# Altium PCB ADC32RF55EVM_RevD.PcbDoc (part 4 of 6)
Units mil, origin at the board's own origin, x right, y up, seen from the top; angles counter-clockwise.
Board outline 4190 x 2750 mil, 14 copper layers (Top Copper, Layer 2 (GND1), Layer 3 (PWR1), Layer 4 (GND2, Layer 5 (PWR2), Layer 6 (GND3), Layer 7 (SIG1), Layer 8 (GND4), Layer 9 (GND5), Layer 10 (SIG2), Layer 11 (GND6), Layer 12 (PWR3), Layer 13 (GND7), Bottom Copper), stack 58.6 mil thick; 427 components, 558 nets, 1902 pads, 1008 vias.
Unrouted connection lines stored in the file: 51.
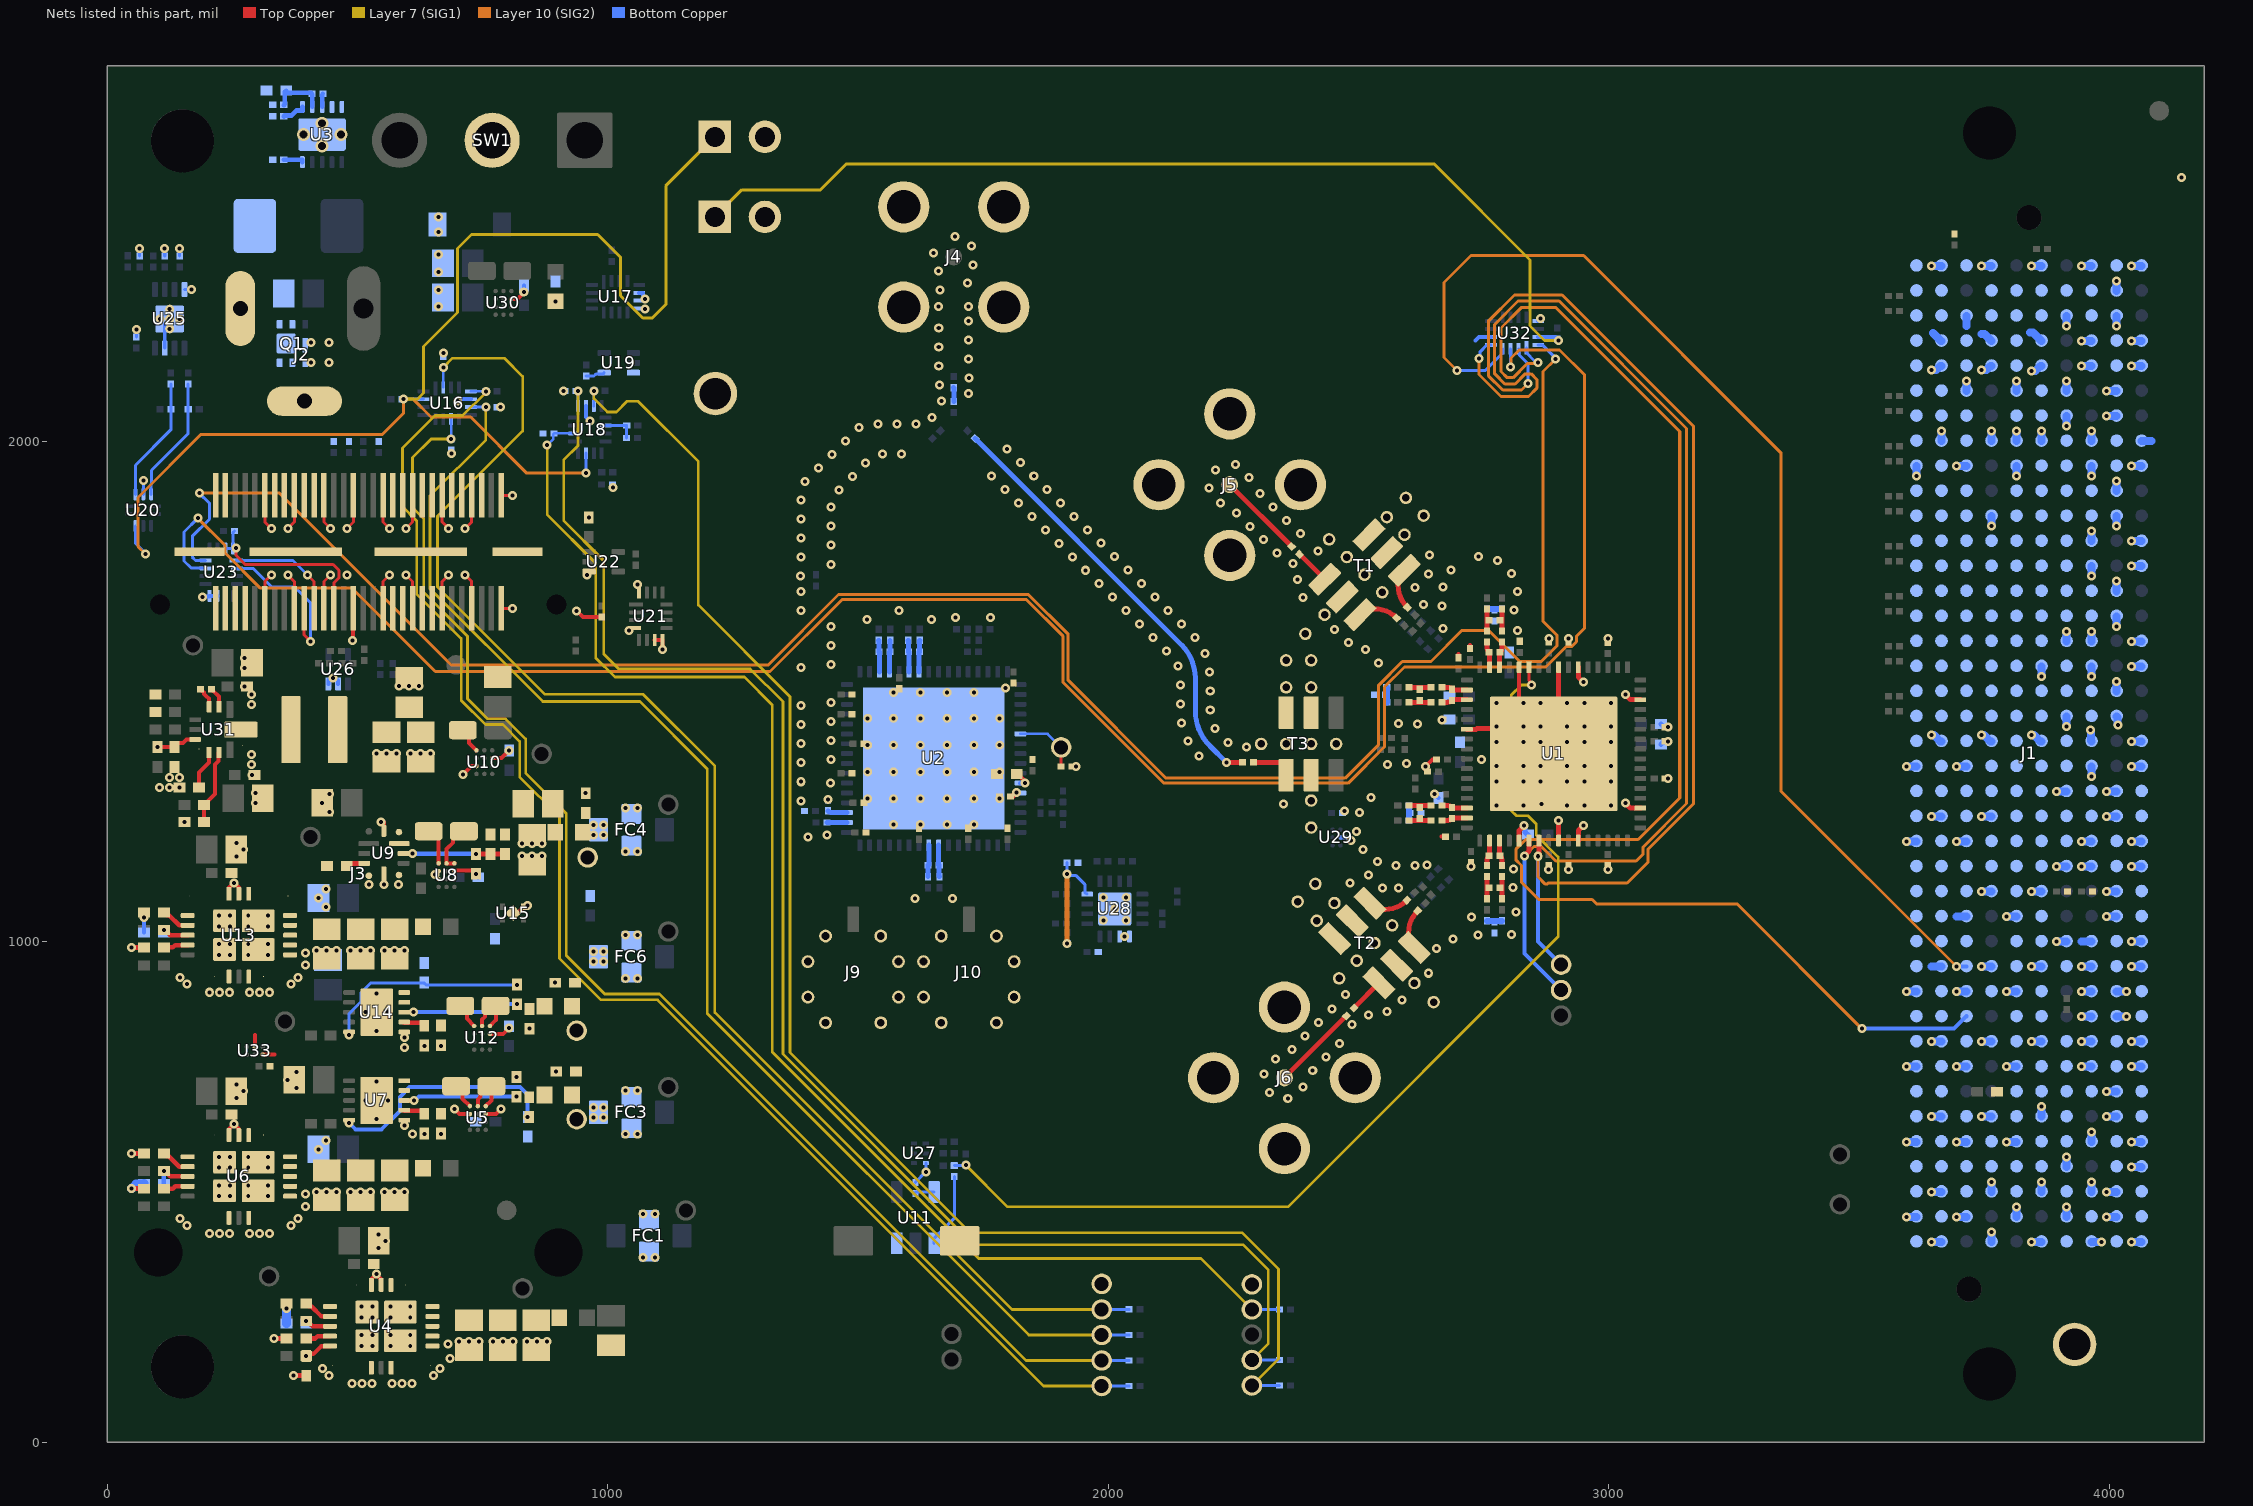
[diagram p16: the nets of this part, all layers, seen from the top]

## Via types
v1: diameter 18, hole 8, Top Copper to Bottom Copper, tented both sides, 1004 vias
v2: diameter 25.75, hole 15.75, Top Copper to Bottom Copper, tented both sides, 4 vias

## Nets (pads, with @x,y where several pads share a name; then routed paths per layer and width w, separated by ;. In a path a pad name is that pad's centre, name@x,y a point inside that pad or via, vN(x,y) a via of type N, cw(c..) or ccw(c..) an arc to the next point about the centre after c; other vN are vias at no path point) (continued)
GND: C1.1 C3.2 C4.2 C5.1 C6.1 C7.1 C8.1 C9.1 C10.1 C11.1 C12.1 C13.1 C14.1 C15.1 C16.1 C17.1 C18.1 C19.1 C20.1 C21.1 C22.1 C23.1 C24.1 C25.1 C26.1 C27.1 C28.1 C29.1 C30.1 C31.1 C32.1 C33.1 C35.1 C39.1 C40.1 C41.1 C42.1 C43.1 C44.1 C45.1 C46.1 C50.1 C51.1 C52.1 C53.1 C54.1 C55.1 C56.1 C57.1 C59.1 C60.1 C64.1 C65.1 C67.1 C71.1 C76.1 C82.1 C91.1 C92.1 C108.1 C109.1 C110.1 C111.1 C112.1 C113.1 C114.1 C115.1 C116.1 C117.1 C118.1 C119.1 C120.1 C121.1 C122.1 C123.1 C124.1 C125.1 C126.1 C127.1 C128.1 C129.1 C130.1 C131.1 C132.1 C139.2 C140.2 C141.2 C142.2 C143.2 C144.2 C145.2 C146.2 C147.2 C148.2 C149.1 C150.1 C151.2 C152.2 C156.1 C159.1 C160.1 C165.1 C166.1 C177.1 C178.1 D2.2 FC1.2 FC3.2 FC4.2 FC6.2 J1.A1 J1.A4 J1.A5 J1.A8 J1.A9 J1.A12 J1.A13 J1.A16 J1.A17 J1.A20 J1.A21 J1.A24 J1.A25 J1.A28 J1.A29 J1.A32 J1.A33 J1.A36 J1.A37 J1.A40 J1.B2 J1.B3 J1.B6 J1.B7 J1.B10 J1.B11 J1.B14 J1.B15 J1.B18 J1.B19 J1.B22 J1.B23 J1.B26 J1.B27 J1.B30 J1.B31 J1.B34 J1.B35 J1.B38 J1.B39 J1.C1 J1.C4 J1.C5 J1.C8 J1.C9 J1.C12 J1.C13 J1.C16 J1.C17 J1.C20 J1.C21 J1.C24 J1.C25 J1.C28 J1.C29 J1.C32 J1.C33 J1.C36 J1.C38 J1.C40 J1.D2 J1.D3 J1.D6 J1.D7 J1.D10 J1.D13 J1.D16 J1.D19 J1.D22 J1.D25 J1.D28 J1.D37 J1.D39 J1.E1 J1.E4 J1.E5 J1.E8 J1.E11 J1.E14 J1.E17 J1.E20 J1.E23 J1.E26 J1.E29 J1.E32 J1.E35 J1.E38 J1.E40 J1.F6 J1.F9 J1.F21 J1.F27 J1.F30 J1.F33 J1.F36 J1.F39 J1.G1 J1.G4 J1.G5 J1.G8 J1.G11 J1.G20 J1.G23 J1.G26 J1.G29 J1.G32 J1.G35 J1.G38 J1.G40 J1.H3 J1.H6 J1.H9 J1.H12 J1.H15 J1.H18 J1.H21 J1.H24 J1.H27 J1.H30 J1.H33 J1.H36 J1.H39 J1.J1 J1.J4 J1.J5 J1.J8 J1.J11 J1.J14 J1.J17 J1.J20 J1.J23 J1.J26 J1.J29 J1.J32 J1.J35 J1.J38 J1.J40 J1.K2 J1.K3 J1.K6 J1.K9 J1.K12 J1.K15 J1.K18 J1.K21 J1.K24 J1.K27 J1.K30 J1.K33 J1.K36 J1.K39 J3.1 J3.2 J3.7 J3.8 J3.13 J3.14 J3.19 J3.20 J3.25 J3.26 J3.31 J3.32 J3.37 J3.38 J3.43 J3.44 J3.49 J3.50 J3.MP1 J3.MP2 J3.MP3 J3.MP4 J4.2 J4.3 J4.4 J4.5 J5.2 J5.3 J5.4 J5.5 J6.2 J6.3 J6.4 J6.5 J7.2 J8.2 J9.2 J10.2 PP14.1 PP19.1 Q1.4 Q1.7 R3.1 R4.2 R7.2 R8.2 R9.1 R10.1 R15.1 R17.1 R18.1 R19.1 R22.1 R30.1 R35.1 R37.1 R38.1 R39.1 R42.2 R43.2 R44.2 R50.2 R51.2 R52.2 R53.2 R54.2 R63.2 R64.2 R75.2 R78.1 R79.2 R83.1 R85.1 R94.2 R95.2 R96.2 R140.1 R145.1 R154.2 R181.1 R182.1 SW3.1 T1.1 T1.2 T1.5 T2.1 T2.2 T2.5 T3.1 T3.2 T3.5 TP3.1 TP4.1 U1.6 U1.8 U1.12 U1.22 U1.37 U1.41 U1.43 U1.51 U1.62 U1.65 U2.65 U3.11 U4.1 U4.2 U4.3 U4.5 U4.6 U4.7 U4.8 U4.9 U4.16 U4.17 U4.20 U4.25 U4.26 U4.28 U5.C1 U5.C3 U6.1 U6.2 U6.3 U6.5 U6.6 U6.7 U6.8 U6.9 U6.16 U6.17 U6.20 U6.25 U6.26 U6.28 U7.6 U7.11 U8.B3 U8.C1 U8.C3 U9.5 U9.6 U9.7 U9.12 U10.B3 U10.C1 U11.3 U12.C1 U13.1 U13.2 U13.3 U13.5 U13.6 U13.7 U13.8 U13.9 U13.16 U13.17 U13.20 U13.25 U13.26 U13.28 U14.6 U14.11 U15.2 U15.5 U16.6 U17.6 U17.7 U17.8 U18.6 U19.3 U20.4 U21.4 U21.7 U21.8 U21.16 U22.3 U23.7 U23.8 U25.4 U25.7 U25.9 U26.2 U26.3 U27.3 U28.1 U28.2 U28.17 U29.B2 U30.C1 U31.5 U31.9 U31.11 U32.6 U32.13 U33.B2 U33.C1 | length 5811.2
  Top Copper w6: J3.50@314.74,1666 314.74,1719.39 v1(327.78,1732.43) ; J3.49@314.74,1891.59 314.74,1838.2 v1(327.78,1825.16) ; v1(360.76,1732.43) 373.8,1719.39 J3.44@373.8,1666 ; v1(360.76,1825.16) 373.8,1838.2 J3.43@373.8,1891.59 ; J3.38@432.85,1666 432.85,1719.39 v1(445.89,1732.43) ; J3.37@432.85,1891.59 432.85,1838.2 v1(445.89,1825.16) ; v1(478.87,1825.16) 491.91,1838.2 J3.31@491.91,1891.59 ; J3.26@550.96,1666 550.96,1719.39 v1(564,1732.43) ; J3.25@550.96,1891.59 550.96,1838.2 v1(564,1825.16) ; v1(596.98,1732.43) 610.02,1719.39 J3.20@610.02,1666 ; v1(596.98,1825.16) 610.02,1838.2 J3.19@610.02,1891.59 ; J3.14@669.07,1666 669.07,1719.39 v1(682.11,1732.43) ; J3.13@669.07,1891.59 669.07,1838.2 v1(682.11,1825.16) ; v1(715.09,1732.43) 728.13,1719.39 J3.8@728.13,1666 ; v1(715.09,1825.16) 728.13,1838.2 J3.7@728.13,1891.59 ; J3.2@787.18,1666 v1(810,1666) ; J3.1@787.18,1891.59 v1(810,1891.59)
  Top Copper w8: U6.17@243.24,613.31 243.24,625.46 v1(253.09,635.31) 262.93,625.46 U6.16@262.93,613.31 ; U13.17@243.24,1095.5 243.24,1107.66 v1(253.09,1117.5) 262.93,1107.66 U13.16@262.93,1095.5 ; U33.B2@294.75,789.75 294.75,813.75 ; U33.C1@310.5,774 334.5,774 ; v1(490,1602) 490.95,1602.95 490.95,1665.05 J3.32@491.91,1666 ; U4.17@527.67,313.95 527.67,326.11 v1(537.51,335.95) 547.36,326.11 U4.16@547.36,313.95 ; v1(547.02,1238.89) 552.73,1238.89 U9.12@552.73,1221.22 ; U8.B3@662.18,1124.89 662.18,1125.12 655.26,1132.04 v1(655.26,1133.63) U8.C3@662.18,1140.64 ; U8.C1@693.68,1140.64 693.91,1140.64 695.1,1141.83 731.09,1141.83 736.94,1135.99 v1(736.94,1135.44) ; v1(693.91,665.28) 703.82,655.37 U5.C3@724.7,655.37 ; v1(711,1333.5) 728.04,1350.54 737.52,1350.54 U10.B3@737.68,1350.71 ; U5.C1@756.19,655.37 777.07,655.37 v1(786.98,665.28) ; U12.C1@764.63,815.58 791.19,815.58 v1(802.7,827.09) v1@802.61,827.18 ; U10.C1@769.18,1366.46 787.92,1366.46 v1(803.14,1381.67) ; U30.C1@807.43,2284.09 819.94,2284.09 v1@832.17,2296.33 ; v1(938,1661) 950.57,1648.43 R85.1@988.21,1648.43 ; v1(1042.33,1621.68) 1042.33,1626.38 U21.4@1054.5,1626.38 ; v1(1059.18,1713.8) 1062.38,1713.8 U21.16@1062.38,1697.24 ; U21.7@1093.87,1602.76 U21.8@1109.62,1602.76 1109.62,1583.87 v1(1109.69,1583.8) ; R154.2@1930.5,1350 v1(1935.5,1350) ; C92.1@2637.95,1340 2633.94,1344.02 v1(2633.94,1350.32) 2647.62,1364 C121.1@2656.95,1364 ; 2666.44,1209.72 C160.1@2671.44,1209.72 ; C111.1@2700,1569.5 2700,1574.5 ; C117.1@2722.96,1588.03 2722.96,1593.03 ; v1(2725,1150.5) C118.1@2725,1155.5 ; U1.12@2821.1,1548.23 2821.1,1485.33 v1(2829.34,1477.17) v1(2829.34,1477.17) ; v1(2880.16,1144.49) C129.1@2880.16,1149.49 ; C130.1@2880.43,1600.74 v1(2880.43,1605.74) ; v1(2919.53,1144.49) C127.1@2919.53,1149.49 ; C126.1@2919.8,1600.74 v1(2919.8,1605.74) ; v1(2998.25,1144.47) C131.1@2998.25,1149.47 ; C128.1@2998.27,1600.51 v1(2998.27,1605.51) ; C125.1@3113.06,1325.79 v1(3118.06,1325.79)
  Top Copper w10: v1(48.7,506.26) R15.1@73.7,506.26 ; v1(48.7,576.26) C30.1@73.7,576.26 ; v1(48.7,988.45) R35.1@73.7,988.45 ; v1(73.7,1048.45) C33.1@73.7,1058.45 ; v1(333.12,206.91) R9.1@358.12,206.91 ; v1(358.12,266.91) C15.1@358.12,276.91 ; v1(372.49,132.54) R8.2@397.49,132.54 ; U15.5@810.94,1056.8 820.01,1056.8 833.51,1070.29 838.6,1070.29 v1(840.13,1071.82) ; C149.1@1777.99,1334.82 1782.23,1339.05 U2.65@1783.2,1339.05 ; U1.22@2716.77,1424.21 2735.26,1424.21 2736.54,1425.5 2771.91,1425.5 v1(2776.27,1429.86) ; U1.37@2821.1,1201.77 2821.1,1221.77 v1(2831.1,1231.77) ; U1.41@2899.84,1201.77 v1(2899.84,1241.77) ; U1.8@2899.84,1548.23 2899.84,1484.33 2907,1477.17 v1(2916.82,1477.17) ; U1.43@2939.21,1201.77 2939.21,1221.77 v1(2949.21,1231.77) ; U1.6@2939.21,1548.23 2939.21,1528.23 v1(2949.21,1518.23) ; v1(3033.23,1276.73) 3043.23,1266.73 U1.51@3063.23,1266.73 ; v1(3033.23,1493.27) 3043.23,1483.27 U1.62@3063.23,1483.27
  Bottom Copper w6: v1(58.12,2222.57) 58.2,2222.48 C67.1@58.2,2208.02 ; v1(64.76,2384.76) 64.84,2384.67 R94.2@64.84,2370.21 ; U20.4@72,1893.5 72.4,1893.89 v1(72.4,1921.7) ; v1(114.76,2384.65) v1(114.76,2384.65) R95.2@114.84,2370.1 ; U25.7@114.84,2185.8 114.84,2234.16 U25.9@124.68,2244 ; v1(144.44,2384.65) 144.53,2384.56 R96.2@144.53,2370.1 ; U25.4@154.21,2303.06 168.67,2303.06 v1(168.76,2303.14) ; C44.1@1614.89,518.55 1614.89,519.33 v1(1635.56,540.01) U27.3@1635.56,557.23
  Bottom Copper w7.87: R39.1@73.7,1018.45 v1(73.7,1048.45)
  Bottom Copper w8: v1(190,1689) 190.88,1689.88 204.31,1689.88 204.38,1689.94 U23.8@204.38,1690.76 ; U23.8@204.38,1690.76 U23.7@220.13,1690.76 ; U26.3@441.63,1514.73 441.63,1522.02 443.54,1523.92 445.72,1523.92 448.38,1526.58 v1(451.08,1526.58) 453.79,1526.58 456.45,1523.92 459.41,1523.92 461.31,1522.02 U26.2@461.31,1514.73 ; v1(700,2080) 703.68,2083.68 U16.6@726.49,2083.68 ; v1(736.94,1135.44) 741.23,1131.15 C32.1@741.23,1128.42 ; v1(832.17,2298.33) 832.43,2298.33 C1.1@832.43,2310.72 ; U18.6@956.44,2070.4 956.44,2048.56 v1(964.96,2040.04) ; U17.6@1062.87,2296.35 1070.61,2296.35 1070.68,2296.28 1070.68,2290.6 1074.57,2286.71 v1(1074.57,2284) ; U29.B2@2464,1208 2464.2,1207.8 2476.51,1207.8 2482.19,1202.12 v1(2484.89,1202.12) ; v1(2651.95,1294.5) 2659.76,1286.69 C91.1@2660,1286.69 ; 2734.15,2201.09 2741.19,2208.13 U32.6@2764.76,2208.13 ; U32.13@2859.24,2239.62 2859.24,2245.35 v1(2864.22,2245.35) 2862.31,2243.44 2862.31,2239.69 2862.25,2239.62 U32.13@2859.24,2239.62
  Bottom Copper w10: v1(2831.1,1231.77) 2832.63,1230.24 2832.63,1218.84 2837.48,1214 C123.1@2838.69,1214 ; C110.1@3104.31,1394 3108.98,1398.67 3116.53,1398.67 v1(3118.06,1400.21) ; C122.1@3104.31,1434.71 3108.98,1430.03 3116.53,1430.03 v1(3118.06,1428.5)
  Bottom Copper w16: v1(3595,450) J1.K39@3615,450 ; v1(3595,600) J1.K36@3615,600 ; v1(3595,750) J1.K33@3615,750 ; v1(3595,900) J1.K30@3615,900 ; v1(3595,1200) J1.K24@3615,1200 ; v1(3595,1350) J1.K21@3615,1350 ; v1(3615,1930) J1.K9@3615,1950 ; v1(3645,400) J1.J40@3665,400 ; v1(3645,500) J1.J38@3665,500 ; v1(3645,650) J1.J35@3665,650 ; v1(3645,800) J1.J32@3665,800 ; 3645,950 J1.J29@3665,950 ; v1(3645,1250) J1.J23@3665,1250 ; v1(3645,1412.5) 3650.01,1412.5 3662.51,1400 J1.J20@3665,1400 ; v1(3645,2142) 3654.51,2142 3662.51,2150 J1.J5@3665,2150 ; v1(3645,2350) J1.J1@3665,2350 ; 3648,2216 3664,2200 J1.J4@3665,2200 ; J1.J8@3665,2000 v1(3665,2020) ; v1(3695,450) J1.H39@3715,450 ; v1(3695,600) J1.H36@3715,600 ; v1(3695,750) J1.H33@3715,750 ; v1(3695,900) J1.H30@3715,900 ; 3695,1050 J1.H27@3715,1050 ; v1(3695,1200) J1.H24@3715,1200 ; v1(3695,1350) J1.H21@3715,1350 ; v1(3695,1950) J1.H9@3715,1950 ; J1.H6@3715,2100 v1(3715,2120) ; 3715,2230 J1.H3@3715,2250 ; v1(3745,650) J1.G35@3765,650 ; v1(3745,800) J1.G32@3765,800 ; v1(3745,950) J1.G29@3765,950 ; v1(3745,1100) J1.G26@3765,1100 ; v1(3745,1250) J1.G23@3765,1250 ; v1(3745,1412.5) 3750.01,1412.5 3762.51,1400 J1.G20@3765,1400 ; v1(3745,2142) 3754.51,2142 3762.51,2150 J1.G5@3765,2150 ; 3745,2214 3751,2214 J1.G4@3765,2200 ; v1(3745,2350) J1.G1@3765,2350 ; J1.G40@3765,400 v1(3765,420) ; J1.G38@3765,500 v1(3765,520) ; v1(3765,1830) J1.G11@3765,1850 ; J1.G8@3765,2000 v1(3765,2020) ; v1(3795,600) J1.F36@3815,600 ; v1(3795,750) J1.F33@3815,750 ; v1(3795,900) J1.F30@3815,900 ; v1(3795,1050) J1.F27@3815,1050 ; J1.F39@3815,450 v1(3815,470) ; v1(3815,1930) J1.F9@3815,1950 ; J1.F6@3815,2100 v1(3815,2120) ; 3842,2217 3848,2217 J1.E4@3865,2200 ; v1(3845,400) J1.E40@3865,400 ; v1(3845,800) J1.E32@3865,800 ; v1(3845,950) J1.E29@3865,950 ; v1(3845,1100) J1.E26@3865,1100 ; v1(3845,1412.5) 3850.01,1412.5 3862.51,1400 J1.E20@3865,1400 ; v1(3845,2140) 3852.51,2140 3862.51,2150 J1.E5@3865,2150 ; v1(3845,2350) J1.E1@3865,2350 ; J1.E38@3865,500 v1(3865,520) ; J1.E35@3865,650 v1(3865,670) ; v1(3865,1530) J1.E17@3865,1550 ; J1.E8@3865,2000 v1(3865,2020) ; v1(3895,1000) J1.D28@3915,1000 ; v1(3895,1150) J1.D25@3915,1150 ; v1(3895,1300) J1.D22@3915,1300 ; J1.D39@3915,450 v1(3915,470) ; J1.D37@3915,550 v1(3915,570) ; v1(3915,1430) J1.D19@3915,1450 ; J1.D16@3915,1600 v1(3915,1620) ; v1(3915,2030) J1.D7@3915,2050 ; J1.D6@3915,2100 v1(3915,2120) ; v1(3915,2230) J1.D3@3915,2250 ; v1(3945,750) J1.C33@3965,750 ; v1(3945,800) J1.C32@3965,800 ; v1(3945,950) J1.C29@3965,950 ; 3945,1000 J1.C28@3965,1000 ; v1(3945,1150) J1.C25@3965,1150 ; v1(3945,1200) J1.C24@3965,1200 ; v1(3945,2150) J1.C5@3965,2150 ; v1(3945,2200) J1.C4@3965,2200 ; v1(3945,2350) J1.C1@3965,2350 ; v1(3962.42,1422.58) 3963.24,1421.76 3963.24,1401.76 J1.C20@3965,1400 ; J1.C40@3965,400 v1(3985,400) ; J1.C38@3965,500 v1(3965,520) ; J1.C36@3965,600 v1(3965,620) ; v1(3965,1330) J1.C21@3965,1350 ; v1(3965,1530) J1.C17@3965,1550 ; J1.C16@3965,1600 v1(3965,1620) ; v1(3965,1730) J1.C13@3965,1750 ; J1.C12@3965,1800 v1(3965,1820) ; v1(3965,1930) J1.C9@3965,1950 ; J1.C8@3965,2000 v1(3965,2020) ; v1(3995,450) J1.B39@4015,450 ; v1(3995,500) J1.B38@4015,500 ; v1(3995,650) J1.B35@4015,650 ; v1(3995,700) J1.B34@4015,700 ; v1(3995,1050) J1.B27@4015,1050 ; v1(3995,1100) J1.B26@4015,1100 ; v1(3995,1250) J1.B23@4015,1250 ; v1(3995,1300) J1.B22@4015,1300 ; v1(3995,2050) J1.B7@4015,2050 ; v1(3995,2100) J1.B6@4015,2100 ; J1.B31@4015,850 v1(4035,850) ; J1.B30@4015,900 v1(4035,900) ; J1.B19@4015,1450 4016.76,1448.24 4016.76,1433.39 v1(4017.58,1432.58) ; J1.B18@4015,1500 v1(4015,1520) ; v1(4015,1630) J1.B15@4015,1650 ; J1.B14@4015,1700 v1(4015,1720) ; v1(4015,1830) J1.B11@4015,1850 ; J1.B10@4015,1900 v1(4015,1920) ; v1(4015,2230) J1.B3@4015,2250 ; J1.B2@4015,2300 v1(4015,2320) ; v1(4045,400) J1.A40@4065,400 ; v1(4045,550) J1.A37@4065,550 ; v1(4045,600) J1.A36@4065,600 ; v1(4045,750) J1.A33@4065,750 ; v1(4045,800) J1.A32@4065,800 ; v1(4045,950) J1.A29@4065,950 ; v1(4045,1000) J1.A28@4065,1000 ; v1(4045,1150) J1.A25@4065,1150 ; v1(4045,1200) J1.A24@4065,1200 ; v1(4045,1350) J1.A21@4065,1350 ; v1(4045,1400) J1.A20@4065,1400 ; v1(4045,1550) J1.A17@4065,1550 ; v1(4045,1600) J1.A16@4065,1600 ; v1(4045,1750) J1.A13@4065,1750 ; v1(4045,1800) J1.A12@4065,1800 ; v1(4045,1950) J1.A9@4065,1950 ; v1(4045,2150) J1.A5@4065,2150 ; v1(4045,2200) J1.A4@4065,2200 ; v1(4045,2350) J1.A1@4065,2350 ; J1.A8@4065,2000 4085,2000
  Bottom Copper w18: v1(48.7,506.26) 57.85,515.42 72.85,515.42 R19.1@73.7,516.26 ; R10.1@358.12,236.91 v1(358.12,266.91)
  other v1: 488.53,117.2 508.53,117.2 528.53,117.2 568.53,117.2 588.53,117.2 608.53,117.2 443.36,133.25 651.35,133.25 429.64,146.97 665.07,146.97 684.74,167.32 680.74,196 702.74,200.63 722.74,200.63 742.74,200.63 770.74,200.63 790.74,200.63 810.74,200.63 838.74,200.63 858.74,200.63 878.74,200.63 542.43,387.75 556.32,401.45 542.43,414.79 204.11,416.56 224.11,416.56 244.11,416.56 284.11,416.56 304.11,416.56 324.11,416.56 158.93,432.6 366.93,432.6 145.21,446.32 380.65,446.32 396.31,470.67 396.31,495.36 418.31,499.99 438.31,499.99 458.31,499.99 486.31,499.99 506.31,499.99 526.31,499.99 554.31,499.99 574.31,499.99 594.31,499.99 422.05,584.92 437.05,602.92 633.43,615.47 667.03,615.47 610.34,615.94 593.43,632.24 258.01,687.5 2358.74,686.84 2322.64,698.71 271.9,701.21 378,707.32 2389.21,709.55 258.01,714.55 359.68,723.61 818.01,729.34 2311.16,734.94 378,739.89 897.08,740.62 2408.68,742.18 2334.21,765.15 2435.55,769.05 2366.75,784.77 593.42,788.5 633.42,791.72 667.03,791.72 2462.42,795.92 593.42,808.5 2393.62,811.64 843.83,825.96 2487.12,833.88 2420.49,838.51 2519.92,853.07 2557.23,860.26 2447.18,865.57 2587.37,883.4 2474.57,893.84 204.11,898.75 224.11,898.75 244.11,898.75 284.11,898.75 304.11,898.75 324.11,898.75 158.93,914.79 366.93,914.79 895.08,917.87 145.21,928.51 380.65,928.51 2640.37,936.72 396.32,952.87 396.32,977.55 418.32,982.18 438.32,982.18 458.32,982.18 486.32,982.18 506.32,982.18 526.32,982.18 554.32,982.18 574.32,982.18 594.32,982.18 2656.27,986.02 2689.01,1005.31 2033,1010 2739.18,1013.23 2806.16,1013.73 2726.18,1048.93 2814.9,1059.34 437.05,1069.11 1613.91,1086.14 1688.91,1086.14 422.05,1087.11 437.05,1105.11 2548.23,1107.36 2579.98,1107.33 2809.01,1108.33 523.2,1113.86 552.45,1113.86 582.25,1113.86 2482.64,1116.81 2520.08,1132.88 2809.59,1145.36 2575.16,1152.25 2613.16,1152.25 2637.16,1153.48 2537.87,1159.55 258.01,1170.29 829,1170.54 849,1170.54 869,1170.54 271.9,1184 2508.96,1184.21 258.01,1197.34 1400.26,1208.83 1438.07,1212.69 2496.45,1220.09 154.15,1238.74 2501.92,1257.7 444.27,1259.12 2471.98,1260.48 2776.27,1272.17 2829.34,1272.17 2916.82,1272.17 2951.23,1272.17 3004.3,1272.17 2349.97,1275.19 2866,1275 295.71,1276.5 429.27,1277.12 1386.16,1281.36 1440.04,1283.95 2525.42,1287.57 444.27,1295.12 295.71,1296.5 956.04,1296.51 104.15,1307.74 124.15,1307.74 144.15,1307.74 1444.9,1316.94 1386.16,1319.36 2776.27,1319.48 2829.34,1319.48 2863.75,1319.48 2916.82,1319.48 2951.23,1319.48 3004.3,1319.48 124.15,1327.74 144.15,1327.74 288.87,1333.2 2776.27,1351.01 2829.34,1351.01 2863.75,1351.01 2916.82,1351.01 2951.23,1351.01 3004.3,1351.01 2558.05,1353.39 287.91,1353.68 2595.99,1355.5 1386.16,1357.36 1445.92,1363.71 2746.06,1364.03 2181.66,1370.45 287.91,1373.68 537.97,1376.11 557.97,1376.11 577.97,1376.11 605.97,1376.11 625.97,1376.11 645.97,1376.11 2276,1388.91 1386.16,1395.36 2238.96,1397.42 2776.27,1398.33 2829.34,1398.33 2863.75,1398.33 2916.82,1398.33 2951.23,1398.33 3004.3,1398.33 2159.23,1401.11 1445.92,1401.71 2213.7,1425.81 2829.34,1429.86 2863.75,1429.86 2916.82,1429.86 2951.23,1429.86 3004.3,1429.86 1386.16,1433.36 2618.14,1434.41 2580.18,1436.04 2146.74,1437 1445.92,1439.71 2666.91,1442.85 2203.88,1462.52 1386.16,1471.36 287.91,1473.32 2144.12,1474.91 2776.27,1477.17 2863.75,1477.17 2951.23,1477.17 3004.3,1477.17 1445.92,1477.71 287.91,1493.32 2203.88,1500.52 1794.87,1507.13 274.3,1509.85 583,1510.46 603,1510.46 623,1510.46 2144.12,1512.91 2202.84,1538.5 274.15,1546.9 1386.16,1547.36 2139.48,1550.63 1445.92,1553.71 2539.99,1556.31 274.15,1566.9 2193.6,1575.36 2116.29,1580.73 2513.78,1583.84 1445.92,1591.71 2480.37,1597.94 2173.17,1607.4 2089.42,1607.6 2817.66,1621.18 2452.39,1623.65 2668.48,1625.91 1445.92,1629.71 2062.55,1634.47 2146.79,1634.75 1517.83,1643.39 1647,1643.39 1695.03,1647.51 1765.08,1647.51 1386.16,1661.36 1582.42,1661.31 2035.68,1661.34 2119.92,1661.62 2810.56,1662.11 2667.25,1670.15 2630.32,1673.72 2388.99,1687.04 2008.81,1688.21 2093.05,1688.49 1386.15,1699.36 2817.37,1699.5 2613.29,1707.69 2668.62,1708.12 1981.94,1715.08 2066.18,1715.36 2377.89,1723.38 1385.27,1730.68 478.87,1732.43 958.91,1732.1 2640.16,1734.56 2805.54,1735.61 1955.07,1741.95 2039.31,1742.23 2684.51,1742.64 1445.92,1753.94 2369.57,1755.83 2777.39,1761.13 1386.16,1768.67 1928.2,1768.82 2012.44,1769.1 2740.21,1769.01 2641.64,1772.53 2337.38,1776.03 2418.84,1780 1445.92,1791.94 1901.33,1795.69 1985.57,1795.97 2310.56,1802.95 1386.16,1806.67 2384.04,1815.23 1874.46,1822.56 1958.7,1822.84 1445.92,1829.94 2283.69,1829.82 2356.55,1841.47 1386.16,1844.67 962.1,1847.49 1847.59,1849.43 1931.83,1849.71 2256.82,1856.69 1445.92,1867.94 2329.68,1868.34 1820.72,1876.3 2224.08,1875.99 1904.96,1876.58 1386.16,1882.67 2302.81,1895.21 1461.75,1902.49 1793.85,1903.17 1878.09,1903.45 1010.5,1907.18 2201.75,1906.73 1394.61,1919.72 2281.78,1926.85 1488.62,1929.36 1766.98,1930.04 1851.22,1930.32 2214.04,1942.68 1421.4,1946.66 2254.19,1952.99 1515.49,1956.23 1824.35,1957.2 1448.27,1973.53 687.74,1975.18 1548.75,1974.59 1586.75,1974.59 1797.48,1984.07 1475.14,2000.4 1502.34,2026.94 1539.61,2034.36 1577.61,2034.36 1615.61,2034.36 1647.73,2047.66 785.62,2068.29 1667.12,2080.34 1721.18,2095.27 911.56,2100.24 1662.44,2112.16 1722.04,2126.07 1661.39,2150.14 407,2157 443,2157 1721.15,2164.06 672.15,2176.44 1661.39,2188.14 407,2197 443,2197 1721.15,2202.06 1661.39,2226.14 1721.15,2240.06 1074.68,2264.06 662,2269 1661.27,2268.94 1721.27,2268.94 662,2302 1663.82,2301.57 1718.72,2315.7 662,2338 1661.27,2339.49 1729.47,2352.14 662,2373 1650.58,2375.95 1726.4,2390.02 1693.64,2409.28 662,2418 662,2448 4145,2527
  other v2: 429.29,2589.94 391.89,2612.58 466.69,2612.58 429.29,2635.22
GPIO1_ADC: PP23.1 U1.39 U32.2 | length 2284.1
  Top Copper w10: v1(2859,1170.5) 2860.47,1171.97 U1.39@2860.47,1201.77
  Layer 10 (SIG2) w6: v1(2839,2115) 2826,2102 2788.38,2102 2759.54,2130.84 2759.54,2239.5 2812.04,2292 2907.05,2292 3169.71,2029.35 3169.71,1275.71 3079.05,1185.05 3079.05,1159.05 3037,1117 2879,1117 2877.49,1115.49 2872.51,1115.49 2859,1129 v1(2859,1170.5)
  Bottom Copper w6: U32.2@2819.87,2184.5 2820.81,2183.57 2820.81,2172.6 2839,2154.41 v1(2839,2115)
  Bottom Copper w8: v1(2859,1170.5) 2859,1000 PP23.1@2905,954
GPIO1_ADC_FMC_H31: J1.H31 U32.1 | length 2891.5
  Layer 10 (SIG2) w6: v1(2859,2157) 2856.7,2154.7 2836.96,2154.7 2809.1,2126.85 2797.31,2126.85 2784.92,2139.24 2784.92,2226.01 2826.25,2267.34 2893.66,2267.34 3142,2019 3142,1287 3059,1204 2834.06,1204 2814.34,1184.28 2814.34,1163.24 2825.59,1151.99 2825.59,1118.41 2860,1084 2967,1084 2976.09,1074.91 3256.92,1074.91 v1(3505.82,826)
  Bottom Copper w6: U32.1@2835.62,2186.47 2835.62,2176.63 2852.96,2159.3 2856.7,2159.3 v1(2859,2157)
  Bottom Copper w8: v1(3505.82,826) 3690,826 J1.H31@3714,850 ; J1.H31@3715,850 J1.H31@3714,850 ; J1.H31@3715,851 J1.H31@3714,850
GPIO1_ADC_FT: J3.40 U23.1 | length 226.5
  Top Copper w6: v1(400.13,1732.43) 413.17,1719.39 J3.40@413.17,1666
  Bottom Copper w6: U23.1@257.53,1761.62 370.93,1761.62 v1(400.13,1732.43)
GPIO1_ADC_USB: U23.12 U32.16 | length 4171.8
  Layer 10 (SIG2) w6: v1(184,1896) 344.07,1896 687.77,1552.29 1319.98,1552.29 1461.04,1693.35 1795.65,1693.35 1795.75,1693.25 1840.9,1693.25 1920,1614.14 1920,1522 2115.43,1326.57 2473.57,1326.57 2540.36,1393.36 2540.36,1512.31 2587.7,1559.66 2644.8,1559.66 2707,1621.86 2760,1621.86 2822.2,1559.66 2865.37,1559.66 2896.43,1590.71 2896.43,1612.37 2868.89,1639.9 2868.89,2138.89 v1(2894,2164)
  Bottom Copper w6: v1(184,1896) 204.04,1875.96 204.04,1843.97 170,1809.92 170,1768 176.38,1761.62 U23.12@196.5,1761.62 ; U32.16@2859.24,2192.38 2867.12,2192.38 2894,2165.5 v1(2894,2164)
GPIO2_ADC: PP24.1 U1.38 U32.5 | length 2425.3
  Top Copper w10: v1(2832,1170.98) 2832,1171.74 2840.79,1180.53 U1.38@2840.79,1201.77
  Layer 10 (SIG2) w6: v1(2741,2165) 2741,2132.99 2784.99,2089 2839.61,2089 2856.27,2105.66 2856.27,2123.25 2845.08,2134.44 2833.29,2134.44 2813.1,2114.26 2792.52,2114.26 2772.33,2134.44 2772.33,2233.19 2818.92,2279.78 2901.22,2279.78 3155.62,2025.38 3155.62,1275.76 3069.05,1189.19 3069.05,1175.05 3055,1161 2894.34,1161 2865.48,1189.86 2850.88,1189.86 v1(2832,1170.98)
  Bottom Copper w6: v1(2741,2165) 2743.3,2167.3 2743.3,2178.79 2756.88,2192.38 U32.5@2764.76,2192.38
  Bottom Copper w8: v1(2832,1170.98) 2832,976 PP24.1@2905,903
GPIO2_ADC_FMC_H29: J1.H29 U32.4 | length 2352.1
  Layer 10 (SIG2) w6: v1(2697,2141) 2671,2167 2671,2317 2725,2371 2950,2371 3344,1977 3344,1301 v1(3695,950)
  Bottom Copper w6: v1(2697,2141) 2697.07,2141.07 2753.37,2141.07 2787.44,2175.15 2787.44,2183.57 U32.4@2788.38,2184.5
  Bottom Copper w8: v1(3695,950) J1.H29@3715,950
GPIO2_ADC_FT: J3.42 U23.2 | length 324.5
  Top Copper w6: J3.42@393.48,1666 393.48,1612.61 v1(406.52,1599.57)
  Bottom Copper w6: U23.2@259.5,1745.87 291.13,1745.87 329,1708 375,1708 406.52,1676.48 v1(406.52,1599.57)
GPIO2_ADC_USB: U23.11 U32.3 | length 4258.2
  Layer 10 (SIG2) w6: v1(181,1846) 235.5,1791.5 235.5,1776.35 305.85,1706 489.13,1706 655.51,1539.62 1324.37,1539.62 1467.99,1683.25 1836.75,1683.25 1910,1610 1910,1517.86 2111.28,1316.57 2479.57,1316.57 2552.27,1389.27 2552.27,1508.94 2591.97,1548.64 2874.25,1548.64 2915.35,1589.74 2926.42,1589.74 2935.8,1599.11 2935.8,1610.18 2952,1626.39 2952,2132 2901.72,2182.28 2821.28,2182.28 2805,2166 2805,2149 v1(2804,2148)
  Bottom Copper w6: v1(181,1846) 181,1845.86 153.43,1818.29 153.43,1760.57 167.19,1746.81 195.57,1746.81 U23.11@196.5,1745.87 ; v1(2804,2148) 2804.06,2148.06 2804.06,2184.44 U32.3@2804.13,2184.5
GPIO_DIR: J3.36 R177.2 U23.15 U23.16 | length 364.5
  Top Copper w6: v1(257.25,1786.17) 257.25,1771.75 275.62,1753.38 451.43,1753.38 462.87,1741.94 462.87,1726.78 452.54,1716.45 J3.36@452.54,1666
  Bottom Copper w6: U23.15@235.87,1785.24 250.68,1785.24 U23.16@251.62,1785.24 251.62,1817.88 R177.2@254.1,1820.35
INA1_ADC_N: C68.2 R104.2 U1.15 | length 51.4
  Top Copper w10: C68.2@2756.89,1598.23 2756.89,1587.83 ccw(c2770.47,1587.83) R104.2@2760.87,1578.23 cw(c2758.01,1575.38) 2762.05,1575.38 U1.15@2762.05,1548.23
INA1_ADC_P: C74.2 R104.1 U1.14 | length 51.4
  Top Copper w10: U1.14@2781.73,1548.23 2781.73,1575.38 cw(c2785.77,1575.38) R104.1@2782.91,1578.23 ccw(c2773.31,1587.83) 2786.89,1587.83 C74.2@2786.89,1598.23
INA2_ADC_N: C78.2 R111.1 U1.19 | length 51.4
  Top Copper w10: C78.2@2666.77,1478.11 2677.17,1478.11 ccw(c2677.17,1491.69) R111.1@2686.77,1482.09 cw(c2689.62,1479.24) 2689.62,1483.27 U1.19@2716.77,1483.27
INA2_ADC_P: C75.2 R111.2 U1.18 | length 51.4
  Top Copper w10: C75.2@2666.77,1508.11 2677.17,1508.11 cw(c2677.17,1494.53) R111.2@2686.77,1504.13 ccw(c2689.62,1506.99) 2689.62,1502.95 U1.18@2716.77,1502.95
INB1_ADC_N: C155.2 R126.2 U1.34 | length 51.4
  Top Copper w10: C155.2@2756.89,1151.77 2756.89,1162.17 cw(c2770.47,1162.17) R126.2@2760.87,1171.77 ccw(c2758.01,1174.62) 2762.05,1174.62 U1.34@2762.05,1201.77
INB1_ADC_P: C158.2 R126.1 U1.35 | length 51.4
  Top Copper w10: U1.35@2781.73,1201.77 2781.73,1174.62 ccw(c2785.76,1174.62) R126.1@2782.91,1171.77 cw(c2773.31,1162.17) 2786.89,1162.17 C158.2@2786.89,1151.77
INB2_ADC_N: C79.2 R119.2 U1.30 | length 51.4
  Top Copper w10: C79.2@2666.77,1271.89 2677.17,1271.89 cw(c2677.17,1258.31) R119.2@2686.77,1267.91 ccw(c2689.62,1270.77) 2689.62,1266.73 U1.30@2716.77,1266.73
INB2_ADC_P: C154.2 R119.1 U1.31 | length 51.4
  Top Copper w10: C154.2@2666.77,1241.89 2677.17,1241.89 ccw(c2677.17,1255.47) R119.1@2686.77,1245.87 cw(c2689.62,1243.01) 2689.62,1247.05 U1.31@2716.77,1247.05
NetC2_2: C2.2 D1.1 J2.2 Q1.1 Q1.2 Q1.5 Q1.6 Q1.8
NetC5_2: C5.2 R2.1 R4.1 U3.2 | length 111.9
  Bottom Copper w9: C5.2@352.68,2671.5 353.29,2671.5 355.09,2673.3 355.09,2697.71 R4.1@357.68,2700.3 ; R4.1@354.96,2697.71 357.09,2695.58 407.12,2695.58 R2.1@408.7,2694 ; U3.2@409.61,2667.7 R2.1@409.61,2693.09
NetC6_2: C6.2 U3.1 | length 48.8
  Bottom Copper w10: C6.2@352.68,2649 353.92,2650.23 367.64,2650.23 378.29,2660.89 389.65,2660.89 389.92,2661.16 U3.1@389.92,2667.7
NetC9_2: C9.2 C10.2 C11.2 FB1.1 U4.10 U4.11 U4.12 U4.13 U4.14 U4.15 U4.27
NetC15_2: C15.2 U4.21 | length 58.2
  Top Copper w9: C15.2@397.49,276.91 402.84,271.56 407.4,271.56 428,250.96 U4.21@444.99,250.96
NetC16_2: C16.2 C17.2 C34.2 FB4.1 R20.2 R21.2 U8.D1 U8.D2 | length 98.4
  Top Copper w8: U8.D1@693.68,1156.38 U8.D2@677.93,1156.38 677.93,1184.91 691.29,1198.27 691.29,1206.44 705.25,1220.4 R20.2@712.62,1220.4
  other v1: 829,1196.4 849,1196.4 869,1196.4
NetC21_2: C21.2 C22.2 C23.2 FB2.1 U6.10 U6.11 U6.12 U6.13 U6.14 U6.15 U6.27
NetC26_2: C26.2 FB3.1 R12.2 R16.2 U5.D1 U5.D2 U7.8 | length 329.2
  Top Copper w8: U5.D2@740.44,671.12 740.44,683.92 ; 740.44,684.42 746.14,690.11 746.14,697.82 760.1,711.78 767.81,711.78 767.81,683.24 ; U5.D1@756.19,671.12 767.81,682.74
  Top Copper w9: U7.8@593.43,682.61 593.43,682.18 v1(612.45,682.18)
  Bottom Copper w8: v1(612.45,682.18) 615.16,682.18 622.95,689.97 v1(818.01,689.97)
NetC27_2: C27.2 FB3.2 FC3.1 PP5.1
  other v1: 971.45,648.63 991.45,648.63 971.45,668.63 991.45,668.63
NetC29_2: C29.2 U31.6 | length 78.3
  Top Copper w8: C29.2@183.52,1307.74 183.52,1338.04 203.52,1358.04 U31.6@203.52,1377.73
NetC30_2: C30.2 U6.21 | length 58.2
  Top Copper w9: C30.2@113.07,576.26 118.41,570.92 122.97,570.92 143.58,550.31 U6.21@160.57,550.31
NetC31_2: C31.2 R17.2 U7.7 | length 44
  Top Copper w9: U7.7@593.43,661.93 628.08,661.93 633.43,656.58 R17.2@633.43,655.84 R17.2@633.43,654.84
NetC33_2: C33.2 U13.21 | length 58.2
  Top Copper w9: C33.2@113.07,1058.45 118.41,1053.11 122.97,1053.11 143.58,1032.51 U13.21@160.57,1032.51
NetC34_1: C34.1 R21.1 R22.2 U9.9 | length 203.5
  Top Copper w8: U9.9@592.1,1175.95 592.1,1176.05 v1(610.2,1176.05)
  Top Copper w10: v1(736.94,1174.81) C34.1@765.94,1174.81 R21.1@794.94,1174.81
  Bottom Copper w9: v1(610.2,1176.05) 610.82,1175.43 736.32,1175.43 v1(736.94,1174.81)
NetC35_2: C35.2 FB4.2 FC4.1 PP7.1
  other v1: 971.37,1212.6 991.37,1212.6 971.37,1232.6 991.37,1232.6
NetC39_2: C39.2 U9.4 | length 35
  Top Copper w10: C39.2@478.36,1156.26 U9.4@513.36,1156.26
NetC41_2: C41.2 C42.2 C43.2 L7.2 R26.1 U10.D3 | length 51.5
  Top Copper w8: R26.1@710.32,1422.36 722.95,1409.73 722.95,1396.94 U10.D3@737.68,1382.2
NetC44_2: C44.2 U11.5 | length 37.4
  Bottom Copper w6: C44.2@1614.89,499.5 U11.5@1652.3,499.5
NetC50_2: C50.2 R143.1 R144.1 U28.8 | length 227.3
  Layer 10 (SIG2) w10: v1(1917.95,995.94) v1(1917.95,1134.73)
  Bottom Copper w6: C50.2@1917.95,1157.73 v1(1917.95,1134.73) 1921.25,1132.39 1932.7,1132.39 cw(c1932.7,1126.39) 1936.92,1130.65 1951.93,1115.64 cw(c1947.69,1111.4) 1953.69,1111.4 1953.69,1096.6 U28.8@1957.95,1094.87
NetC54_2: C54.2 C55.2 C56.2 FB5.1 U13.10 U13.11 U13.12 U13.13 U13.14 U13.15 U13.27
NetC59_2: C59.2 FB6.1 R32.2 R36.2 U12.D1 U12.D2 U14.8 | length 340.8
  Top Copper w8: U14.8@593.42,858.97 v1(611.53,858.97) ; U12.D2@748.88,831.32 748.88,844.12 754.57,849.81 754.57,857.52 768.53,871.48 R32.2@775.85,871.48 776.24,871.48 776.24,842.94 U12.D1@764.63,831.32
  Top Copper w9: R32.2@767.98,870.48 R32.2@776.24,870.48
  Bottom Copper w8: v1(611.53,858.97) 758.97,858.97 774.8,874.8 v1(818.43,874.8)
NetC60_2: C60.2 FB6.2 FC6.1 PP11.1
  other v1: 971.45,959.89 991.45,959.89 971.45,979.89 991.45,979.89
NetC64_2: C64.2 R37.2 U14.7 | length 44
  Top Copper w9: U14.7@593.42,838.18 628.08,838.18 633.42,832.84 R37.2@633.42,831.97 R37.2@633.42,831.09
NetC68_1: C68.1 C72.2 R101.2 | length 44.1
  Top Copper w10: C68.1@2756.89,1620.28 R101.2@2756.89,1664.35
NetC69_1: C69.1 J5.1 | length 175
  Top Copper w10: J5.1@2242.79,1912.98 C69.1@2366.5,1789.27
NetC69_2: C69.2 T1.6 | length 70.1
  Top Copper w10: C69.2@2382.9,1773.68 T1.6@2432.49,1724.08
NetC70_1: C70.1 T1.4 | length 86.7
  Top Copper w10: T1.4@2502.39,1652.56 cw(c2532.4,1622.55) 2532.4,1664.99 cw(c2532.4,1602.96) 2576.26,1646.82 C70.1@2576.45,1646.62 C70.1@2573.39,1649.69
NetC71_2: C71.2 R102.1 R105.2 | length 30
  Bottom Copper w12: R102.1@2756.89,1664.35 R105.2@2786.89,1664.35
NetC72_1: C72.1 C74.1 R107.2 | length 44.1
  Top Copper w10: C74.1@2786.89,1620.28 R107.2@2786.89,1664.35
NetC73_1: C73.1 T1.3 | length 86.7
  Top Copper w10: T1.3@2591.73,1741.9 ccw(c2621.74,1711.89) 2579.3,1711.89 ccw(c2641.33,1711.89) 2597.47,1668.03 C73.1@2597.67,1667.84 C73.1@2594.6,1670.9
NetC75_1: C75.1 C77.2 R109.2 | length 44.1
  Top Copper w10: R109.2@2600.65,1508.11 C75.1@2644.72,1508.11
NetC76_2: C76.2 R110.1 R112.2 | length 30
  Bottom Copper w12: R112.2@2556.56,1478.11 R110.1@2556.56,1508.11
NetC77_1: C77.1 C78.1 R114.2 | length 44.1
  Top Copper w10: R114.2@2600.65,1478.11 C78.1@2644.72,1478.11
NetC79_1: C79.1 C83.2 R116.2 | length 44.1
  Top Copper w10: R116.2@2600.65,1271.89 2622.68,1271.89 C79.1@2644.72,1271.89
NetC80_1: C80.1 J6.1 | length 175
  Top Copper w10: J6.1@2352.02,727.79 C80.1@2475.73,851.5
NetC80_2: C80.2 T2.6 | length 70.1
  Top Copper w10: C80.2@2491.32,867.9 T2.6@2540.92,917.49
NetC81_1: C81.1 T2.3 | length 86.7
  Top Copper w10: T2.3@2523.1,1076.73 ccw(c2553.11,1106.74) 2553.11,1064.3 ccw(c2553.11,1126.33) 2596.97,1082.47 C81.1@2597.16,1082.67 C81.1@2594.1,1079.6
NetC82_2: C82.2 R117.1 R120.2 | length 30
  Bottom Copper w12: R120.2@2600.65,1241.89 2600.65,1256.9 R117.1@2600.65,1271.89
NetC83_1: C83.1 C154.1 R122.2 | length 44.1
  Top Copper w10: R122.2@2600.65,1241.89 C154.1@2644.72,1241.89
NetC99_1: C99.1 T2.4 | length 86.7
  Top Copper w10: T2.4@2612.44,987.39 cw(c2642.45,1017.4) 2600.01,1017.4 cw(c2662.04,1017.4) 2618.18,1061.26 C99.1@2618.38,1061.45 C99.1@2615.31,1058.39
NetC101_1: C101.1 R132.2 | length 878.8
  Top Copper w10: v1(2235.9,1358.23) C101.1@2268.51,1358.23
  Bottom Copper w10: R132.2@1734.25,2005.03 2146.22,1593.06 cw(c2079.17,1526) 2174,1526 2174,1461.55 ccw(c2274,1461.55) 2203.29,1390.84 v1(2235.9,1358.23)
NetC101_2: C101.2 T3.6 | length 85.1
  Top Copper w10: C101.2@2290.55,1358.23 2345.55,1358.23 2355.51,1348.27 T3.6@2355.51,1332.26
NetC103_2: C103.2 R134.1 | length 27.6
  Bottom Copper w10: C103.2@1691.27,2106.68 1691.38,2106.57 1691.38,2079.26 R134.1@1691.49,2079.15
NetC107_1: C107.1 U2.34 | length 40
  Bottom Copper w10: C107.1@1438.09,1237.87 U2.34@1478.09,1237.87
NetC108_2: C108.2 U2.35 | length 39.1
  Bottom Copper w10: C108.2@1440.04,1261.37 ccw(c1449.25,1270.58) 1449.25,1257.56 U2.35@1478.09,1257.56
NetC133_1: C133.1 R151.1 U2.24 | length 64.2
  Bottom Copper w10: U2.24@1661.16,1192.6 1661.16,1153.78 ccw(c1662.34,1153.78) R151.1@1662.34,1152.6 1662.34,1129.6 C133.1@1662.82,1129.6
NetC134_1: C134.1 R151.2 U2.25 | length 64.2
  Bottom Copper w10: C134.1@1639.81,1129.6 1640.29,1129.6 R151.2@1640.29,1152.6 ccw(c1640.29,1153.78) 1641.47,1153.78 U2.25@1641.47,1192.6
NetC135_1: C135.1 R152.1 U2.51 | length 64.2
  Bottom Copper w10: C135.1@1541.39,1602.05 1541.87,1602.05 R152.1@1541.87,1579.05 cw(c1541.87,1577.87) 1543.05,1577.87 U2.51@1543.05,1539.05
NetC136_1: C136.1 R152.2 U2.52 | length 64.2
  Bottom Copper w10: U2.52@1562.73,1539.05 1562.73,1577.87 cw(c1563.91,1577.87) R152.2@1563.91,1579.05 1563.91,1602.05 C136.1@1564.39,1602.05
NetC137_1: C137.1 R153.1 U2.54 | length 64.2
  Bottom Copper w10: C137.1@1600.44,1602.05 1600.92,1602.05 R153.1@1600.92,1579.05 cw(c1600.92,1577.87) 1602.1,1577.87 U2.54@1602.1,1539.05
NetC138_1: C138.1 R153.2 U2.55 | length 64.2
  Bottom Copper w10: U2.55@1621.79,1539.05 1621.79,1577.87 cw(c1622.97,1577.87) R153.2@1622.97,1579.05 1622.97,1602.05 C138.1@1623.44,1602.05
NetC149_2: C149.2 U2.11 | length 35.5
  Top Copper w9: C149.2@1817.36,1334.82 1819.33,1334.82 1832.28,1321.87 1832.28,1318.72 v1(1834,1317)
  Bottom Copper w9: U2.11@1824.54,1316.61 1833.61,1316.61 v1(1834,1317)
NetC150_2: C150.2 U2.12 | length 14.9
  Top Copper w10: C150.2@1804.88,1289.8 1808.76,1289.8 v1(1816.57,1297.61)
NetC155_1: C155.1 C157.2 R124.2 | length 44.1
  Top Copper w10: R124.2@2756.89,1085.65 2756.89,1107.68 C155.1@2756.89,1129.72
NetC156_2: C156.2 R125.1 R130.2 | length 30
  Bottom Copper w12: R125.1@2756.89,1041.56 R130.2@2786.89,1041.56
NetC157_1: C157.1 C158.1 R164.2 | length 44.1
  Top Copper w10: R164.2@2786.89,1085.65 2786.89,1107.68 C158.1@2786.89,1129.72
NetC164_1: C164.1 U31.13 | length 41.5
  Top Copper w8: C164.1@208.52,1504.26 209.3,1504.26 211.6,1501.96 211.6,1501.18 223.2,1489.58 U31.13@223.2,1469.26
NetC164_2: C164.2 U31.14 | length 42.6
  Top Copper w8: C164.2@186.47,1504.26 187.26,1504.26 189.55,1501.96 189.55,1501.18 193.43,1497.3 193.43,1494.65 198.12,1489.96 198.21,1489.96 202.9,1485.28 202.9,1469.88 U31.14@203.52,1469.26
NetD3_2: D3.2 R7.1
  other v1: 895.56,2279.25
NetJ1_A22: J1.A22
NetJ1_A23: J1.A23
NetJ1_A26: J1.A26
NetJ1_A27: J1.A27
NetJ1_A30: J1.A30
NetJ1_A31: J1.A31
NetJ1_A34: J1.A34
NetJ1_A35: J1.A35
NetJ1_A38: J1.A38
NetJ1_A39: J1.A39
NetJ1_B1: J1.B1
NetJ1_B4: J1.B4
NetJ1_B5: J1.B5
NetJ1_B8: J1.B8
NetJ1_B9: J1.B9
NetJ1_B24: J1.B24
NetJ1_B25: J1.B25
NetJ1_B28: J1.B28
NetJ1_B29: J1.B29
NetJ1_B32: J1.B32
NetJ1_B33: J1.B33
NetJ1_B36: J1.B36
NetJ1_B37: J1.B37
NetJ1_B40: J1.B40
NetJ1_C2: J1.C2
NetJ1_C3: J1.C3
NetJ1_C10: J1.C10
NetJ1_C11: J1.C11
NetJ1_C14: J1.C14
NetJ1_C15: J1.C15
NetJ1_C18: J1.C18
NetJ1_C19: J1.C19
NetJ1_C22: J1.C22
NetJ1_C23: J1.C23
NetJ1_C30: J1.C30 R71.1 | length 20
  Bottom Copper w16: v1(3945,900) J1.C30@3965,900
NetJ1_C31: J1.C31 R72.1 | length 20
  Bottom Copper w16: v1(3945,850) J1.C31@3965,850
NetJ1_C34: J1.C34
NetJ1_C39: J1.C39
NetJ1_D8: J1.D8
NetJ1_D9: J1.D9
NetJ1_D11: J1.D11
NetJ1_D12: J1.D12
NetJ1_D14: J1.D14
NetJ1_D15: J1.D15
NetJ1_D17: J1.D17
NetJ1_D18: J1.D18
NetJ1_D20: J1.D20
NetJ1_D21: J1.D21
NetJ1_D23: J1.D23
NetJ1_D24: J1.D24
NetJ1_D29: J1.D29
NetJ1_D32: J1.D32
NetJ1_D33: J1.D33
NetJ1_D34: J1.D34
NetJ1_D35: J1.D35
NetJ1_D36: J1.D36
NetJ1_D38: J1.D38
NetJ1_D40: J1.D40
NetJ1_E2: J1.E2
NetJ1_E3: J1.E3
NetJ1_E6: J1.E6
NetJ1_E7: J1.E7
NetJ1_E9: J1.E9
NetJ1_E10: J1.E10
NetJ1_E12: J1.E12
NetJ1_E13: J1.E13
NetJ1_E15: J1.E15
NetJ1_E16: J1.E16
NetJ1_E18: J1.E18
NetJ1_E19: J1.E19
NetJ1_E21: J1.E21
NetJ1_E22: J1.E22
NetJ1_E24: J1.E24
NetJ1_E25: J1.E25
NetJ1_E27: J1.E27
NetJ1_E28: J1.E28
NetJ1_E30: J1.E30
NetJ1_E31: J1.E31
NetJ1_E33: J1.E33
NetJ1_E34: J1.E34
NetJ1_E36: J1.E36
NetJ1_E37: J1.E37
NetJ1_F2: J1.F2
NetJ1_F3: J1.F3
NetJ1_F4: J1.F4
NetJ1_F5: J1.F5
NetJ1_F7: J1.F7
NetJ1_F8: J1.F8 | length 20
  Bottom Copper w16: J1.F8@3815,2000 v1(3815,2020)
NetJ1_F10: J1.F10
NetJ1_F11: J1.F11
NetJ1_F12: J1.F12
NetJ1_F13: J1.F13
NetJ1_F14: J1.F14
NetJ1_F15: J1.F15
NetJ1_F16: J1.F16
NetJ1_F17: J1.F17
NetJ1_F18: J1.F18
NetJ1_F19: J1.F19
NetJ1_F20: J1.F20
NetJ1_F22: J1.F22
NetJ1_F23: J1.F23
NetJ1_F24: J1.F24
NetJ1_F25: J1.F25
NetJ1_F26: J1.F26
NetJ1_F28: J1.F28
NetJ1_F29: J1.F29
NetJ1_F31: J1.F31
NetJ1_F32: J1.F32
NetJ1_F34: J1.F34
NetJ1_F35: J1.F35
NetJ1_F37: J1.F37
NetJ1_F38: J1.F38
NetJ1_G2: J1.G2
NetJ1_G3: J1.G3
NetJ1_G12: J1.G12
NetJ1_G13: J1.G13
NetJ1_G14: J1.G14
NetJ1_G15: J1.G15
NetJ1_G16: J1.G16
NetJ1_G17: J1.G17
NetJ1_G18: J1.G18
NetJ1_G19: J1.G19
NetJ1_G21: J1.G21
NetJ1_G22: J1.G22
NetJ1_G24: J1.G24
NetJ1_G25: J1.G25
NetJ1_G30: J1.G30
NetJ1_G36: J1.G36
NetJ1_G37: J1.G37
NetJ1_H1: J1.H1
NetJ1_H4: J1.H4
NetJ1_H5: J1.H5
NetJ1_H7: J1.H7
NetJ1_H8: J1.H8
NetJ1_H10: J1.H10
NetJ1_H11: J1.H11
NetJ1_H13: J1.H13
NetJ1_H14: J1.H14
NetJ1_H16: J1.H16
NetJ1_H17: J1.H17
NetJ1_H19: J1.H19
NetJ1_H20: J1.H20
NetJ1_H22: J1.H22
NetJ1_H23: J1.H23
NetJ1_H25: J1.H25
NetJ1_H26: J1.H26
NetJ1_H28: J1.H28
NetJ1_H32: J1.H32
NetJ1_H35: J1.H35
NetJ1_H37: J1.H37
NetJ1_H38: J1.H38
NetJ1_J2: J1.J2
NetJ1_J3: J1.J3
NetJ1_J6: J1.J6
NetJ1_J7: J1.J7
NetJ1_J9: J1.J9
NetJ1_J10: J1.J10
NetJ1_J12: J1.J12
NetJ1_J13: J1.J13
NetJ1_J15: J1.J15
NetJ1_J16: J1.J16
NetJ1_J18: J1.J18
NetJ1_J19: J1.J19
NetJ1_J21: J1.J21
NetJ1_J22: J1.J22
NetJ1_J24: J1.J24
NetJ1_J25: J1.J25
NetJ1_J27: J1.J27
NetJ1_J28: J1.J28
NetJ1_J30: J1.J30
NetJ1_J31: J1.J31
NetJ1_J33: J1.J33
NetJ1_J34: J1.J34
NetJ1_J36: J1.J36
NetJ1_J37: J1.J37
NetJ1_J39: J1.J39
NetJ1_K1: J1.K1
NetJ1_K4: J1.K4
NetJ1_K5: J1.K5
NetJ1_K7: J1.K7
NetJ1_K8: J1.K8
NetJ1_K10: J1.K10
NetJ1_K11: J1.K11
NetJ1_K13: J1.K13
NetJ1_K14: J1.K14
NetJ1_K16: J1.K16
NetJ1_K17: J1.K17
NetJ1_K19: J1.K19
NetJ1_K20: J1.K20
NetJ1_K22: J1.K22
NetJ1_K23: J1.K23
NetJ1_K25: J1.K25
NetJ1_K26: J1.K26
NetJ1_K28: J1.K28
NetJ1_K29: J1.K29
NetJ1_K31: J1.K31
NetJ1_K32: J1.K32
NetJ1_K34: J1.K34
NetJ1_K35: J1.K35
NetJ1_K37: J1.K37
NetJ1_K38: J1.K38
NetJ1_K40: J1.K40
NetJ2_3: J2.3
NetJ3_5: J3.5
NetJ3_9: J3.9
NetJ3_11: J3.11
NetJ3_15: J3.15
NetJ3_16: J3.16
NetJ3_17: J3.17
NetJ3_18: J3.18
NetJ3_21: J3.21
NetJ3_22: J3.22
NetJ3_23: J3.23
NetJ3_24: J3.24
NetJ3_39: J3.39
NetJ3_41: J3.41
NetJ3_45: J3.45
NetJ3_47: J3.47
NetJ3_54: J3.54
NetJ3_56: J3.56
NetJ3_57: J3.57
NetJ3_58: J3.58
NetJ3_59: J3.59
NetJ3_60: J3.60
NetJ7_1: J7.1 R66.1 U16.15 U18.15 U20.10 | length 2608.6
  Layer 10 (SIG2) w6: v1(76.17,1774.25) 61.44,1788.98 61.44,1887.44 187.48,2013.48 549.82,2013.48 592,2055.66 v1(592,2083.68) 611.19,2083.68 646.88,2047.99 726.01,2047.99 838.09,1935.91 v1(956.44,1935.91)
  Layer 7 (SIG1) w6: v1(592,2083.68) 619.68,2083.68 632,2096 632,2189 699.93,2256.93 699.93,2385.02 727.91,2413 980,2413 1025.43,2367.57 1025.43,2290.68 1070.11,2246 1089,2246 1116,2273 1116,2510 J7.1@1214,2608
  Bottom Copper w6: U20.10@56.25,1830.5 56.25,1795.75 76.17,1775.83 v1(76.17,1774.25) ; v1(592,2083.68) U16.15@632,2083.68 ; v1(956.44,1935.91) U18.15@956.44,1975.91
NetJ8_1: J8.1 R65.1 U32.15 | length 1993.2
  Layer 7 (SIG1) w6: J8.1@1214,2448 1268,2502 1425,2502 1477,2554 2651,2554 2843,2362 2843,2230 2871.81,2201.19 v1(2899.86,2201.19)
  Bottom Copper w8: U32.15@2859.24,2208.13 2892.83,2208.13 2893.91,2207.04 2894.7,2207.04 2897,2204.74 R65.1@2897,2203.95
NetL7_1: L7.1 U31.10
NetPP15_1: PP15.1 R45.1 R50.1 U16.2 | length 2980.7
  Layer 7 (SIG1) w5.5: v1(671.37,2147.31) 689.78,2165.72 793.28,2165.72 830,2129 830,2020 660,1850 660,1708.68 874.68,1494 1071,1494 1214,1351 1214,858.51 1807.51,265 PP15.1@1987,265
  Bottom Copper w5: U16.2@671.37,2107.31 v1(671.37,2147.31)
  Bottom Copper w5.5: PP15.1@1987,265 R45.1@2042,265
NetPP16_1: PP16.1 R41.2 R46.1 U16.5 | length 2906.8
  Layer 7 (SIG1) w5.5: v1(756.49,2099.43) 756.49,2097.49 710,2051 654.94,2051 590,1986.06 590,1869.22 618.27,1840.95 618.27,1694.73 707.14,1605.86 707.14,1482.19 755.71,1433.62 790.38,1433.62 824.06,1399.94 824.06,1329.01 903.41,1249.66 903.41,966.59 986.44,883.56 1099.17,883.56 1870.73,112 PP16.1@1987,112
  Bottom Copper w5.5: U16.5@726.49,2099.43 v1(756.49,2099.43) ; PP16.1@1987,112 R46.1@2042,112
NetPP17_1: PP17.1 R48.1 R51.1 U16.7 | length 2739.9
  Layer 7 (SIG1) w5.5: v1(756.49,2067.94) 756.49,2002.49 645.06,1891.06 645.06,1704.94 870.37,1479.63 1064.37,1479.63 1198.86,1345.14 1198.86,856.55 1841.41,214 PP17.1@1987,214
  Bottom Copper w5.5: U16.7@726.49,2067.94 v1(756.49,2067.94) ; PP17.1@1987,214 R48.1@2042,214
NetPP18_1: PP18.1 R49.1 R52.1 U16.10 | length 2737.6
  Layer 7 (SIG1) w5.5: v1(687.12,2004.31) 647.28,2004.31 610,1967.04 610,1867.42 632.51,1844.91 632.51,1697.49 720,1610 720,1485.22 760.22,1445 796.01,1445 836,1405.01 836,1383 836,1337 917,1256 917,972.47 993.99,895.48 1103.05,895.48 1835.53,163 PP18.1@1987,163
  Bottom Copper w5.5: v1(687.12,2004.31) 687.12,2019.31 U16.10@687.12,2044.31 687.12,2045.12 U16.10@688,2046 ; PP18.1@1987,163 R49.1@2042,163
NetPP20_1: PP20.1 R58.1 R63.1 U18.2 | length 2845.6
  Layer 7 (SIG1) w5.5: v1(879,1992) 879,1853 976,1756 976,1748.87 976,1566.92 1014.45,1528.47 1272.99,1528.47 1328.75,1472.7 1328.75,779.52 1741.27,367 2185,367 PP20.1@2287,265
  Bottom Copper w5: v1(879,1992) 891.41,2004.41 891.41,2013.88 R63.1@892.82,2015.28 U18.2@932.82,2015.28
  Bottom Copper w6: PP20.1@2287,265 R58.1@2342,265
NetPP21_1: PP21.1 R59.1 R64.1 U18.5 | length 3099.5
  Layer 7 (SIG1) w5.5: v1(940.69,2100.4) 940.69,1990.69 912,1962 912,1841 992,1761 992,1575 1022,1545 1284.58,1545 1350,1479.58 1350,775.46 1731.39,394.06 2269.94,394.06 2320,344 2320,197 PP21.1@2287,164
  Bottom Copper w5.5: U18.5@940.69,2070.4 v1(940.69,2100.4) ; PP21.1@2287,164 R59.1@2342,164
NetPP22_1: PP22.1 R56.2 R61.1 U18.7 | length 3045.4
  Layer 7 (SIG1) w5.5: v1(972.19,2100.4) 972.19,2085.14 999.25,2058.07 1017.22,2058.07 1038.87,2079.72 1060.28,2079.72 1181,1959 1181,1672.68 1364.41,1489.27 1364.41,778.59 1725,418 2268,418 2340,346 2340,166 PP22.1@2287,113
  Bottom Copper w5.5: U18.7@972.19,2070.4 v1(972.19,2100.4) ; PP22.1@2287,113 R61.1@2342,113
NetPP31_1: PP31.1 R154.1 U2.6 | length 130.7
  Top Copper w6: R154.1@1906,1350 PP31.1@1906,1388
  Bottom Copper w5.5: U2.6@1824.54,1415.04 1878.96,1415.04 PP31.1@1906,1388
NetR2_2: R2.2 SW1.2 U3.3 U3.4 U3.5 | length 26.9
  Bottom Copper w9: U3.3@429.29,2667.7 429.29,2692.54 R2.2@430.75,2694
NetR3_2: R3.2 U3.10 | length 42.3
  Bottom Copper w9: R3.2@352.62,2562.46 389.92,2562.46 U3.10@389.92,2557.46
NetR5_2: R5.2 R8.1 U4.24 | length 55.8
  Top Copper w9: v1(397.49,171.91) 401.55,175.96 412.06,175.96 428,191.91 U4.24@444.99,191.91
NetR6_1: R6.1 R10.2 U4.22 | length 51.9
  Top Copper w9: v1(397.49,241.91) 399.46,241.91 404.81,236.56 410.08,231.28 U4.22@444.99,231.28
NetR9_2: R9.2 U4.23 | length 49.4
  Top Copper w9: R9.2@397.49,206.91 415.6,206.91 420.29,211.59 U4.23@444.99,211.59
NetR12_1: R12.1 U5.D3 U7.9 U7.10 | length 51.5
  Top Copper w8: R12.1@697.33,711.78 709.96,699.15 709.96,686.35 ; 709.96,685.85 U5.D3@724.7,671.12
NetR14_1: R14.1 R19.2 U6.22 | length 71.9
  Top Copper w9: v1(113.07,541.26) 115.04,541.26 120.38,535.92 125.65,530.63 U6.22@160.57,530.63
  Bottom Copper w9: R19.2@113.07,516.26 v1@113.07,536.26
NetR15_2: R15.2 U6.23 | length 49.4
  Top Copper w9: R15.2@113.07,506.26 131.17,506.26 135.86,510.94 U6.23@160.57,510.94
NetR16_1: R16.1 R18.2 U7.5 | length 470.5
  Top Copper w5: v1(483.19,637.52) U7.5@483.19,643.24
  Bottom Copper w8: v1(483.19,637.52) 495.7,625 548.22,625 584.52,661.3 584.52,689.79 604.36,709.63 824.79,709.63 840.08,694.34 v1(840.08,649.71)
NetR20_1: R20.1 U8.D3 U9.10 U9.11 | length 75.8
  Top Copper w8: R20.1@642.14,1220.4 648.06,1220.4 662.02,1206.44 662.02,1156.55 U8.D3@662.18,1156.38
NetR27_1: R27.1 R30.2 U31.4 | length 81.3
  Top Copper w8: v1(100.46,1388.5) 133.5,1388.5 141.31,1396.31 150.85,1396.31 158.35,1403.82 U31.4@175.46,1403.82
NetR28_2: R28.2 R29.2 R133.2 U1.11 | length 2087
  Top Copper w6: U1.11@2840.79,1548.23 2840.79,1521.4 2846.19,1516 v1(2846.19,1512.75)
  Layer 7 (SIG1) w5.5: v1(1715.41,553.21) 1798.62,470 2359.37,470 2899,1009.63 2899,1169.18 2855.18,1213 2855.18,1234.78 2838.5,1251.45 2815.71,1251.45 2805.16,1262 2805.16,1492.16 2825.75,1512.75 v1(2846.19,1512.75)
  Bottom Copper w6: R133.2@1692.41,552.26 1692.89,552.74 1714.93,552.74 v1(1715.41,553.21)
NetR29_1: R29.1 U11.1 | length 149.7
  Bottom Copper w6: U11.1@1652.3,397.14 1652.3,406.98 1692.41,447.09 R29.1@1692.41,530.21
NetR32_1: R32.1 U12.D3 U14.9 U14.10 | length 51.5
  Top Copper w8: R32.1@705.77,871.48 718.4,858.85 718.4,846.06 U12.D3@733.13,831.32
NetR34_1: R34.1 R39.2 U13.22 | length 51.9
  Top Copper w9: v1(113.07,1023.45) 115.04,1023.45 120.38,1018.11 125.65,1012.82 U13.22@160.57,1012.82
NetR35_2: R35.2 U13.23 | length 49.4
  Top Copper w9: R35.2@113.07,988.45 131.17,988.45 135.86,993.14 U13.23@160.57,993.14
NetR36_1: R36.1 R38.2 U14.5 | length 420.6
  Top Copper w5: v1(483.19,813.77) U14.5@483.19,819.5
  Bottom Copper w6: v1(483.19,813.77) 483.19,855.98 507.27,880.06 507.27,898.12 526.83,917.68 R38.2@633.19,917.68 ; R38.2@633.42,916.92 637.18,913.17 v1(818.43,913.17)
NetR57_2: R57.2 R62.1 U18.10 | length 67.2
  Bottom Copper w5.5: U18.10@995.81,2031.03 R57.2@1038,2031 1037.59,2030.65 R62.1@1037.59,2006.17
NetR60_1: R60.1 U19.4 | length 38.7
  Bottom Copper w6: R60.1@957.02,2130.08 972.32,2130.08 976.07,2133.83 990.06,2133.83 U19.4@992.97,2136.73
NetR68_1: R68.1 R73.1 U20.3 | length 249.6
  Bottom Copper w6: U20.3@56.25,1893.5 56.25,1951.72 127.03,2022.49 R68.1@127.03,2063.76 R73.1@127.03,2113.76
NetR69_1: R69.1 R77.1 U20.5 | length 250.9
  Bottom Copper w6: U20.5@87.75,1893.5 87.75,1914.42 88.4,1915.07 88.4,1941.66 161.71,2014.97 R69.1@161.71,2063.76 R77.1@161.71,2113.76
NetR76_1: R76.1 R78.2 U31.7 | length 151.3
  Top Copper w8: R78.2@193.52,1238.74 R76.1@193.52,1272.74 215.29,1294.51 215.29,1353.75 222.28,1360.75 222.28,1376.81 U31.7@223.2,1377.73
